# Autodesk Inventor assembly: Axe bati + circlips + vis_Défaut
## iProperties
Shininess: 64.0
Length Units: 11269
Angle Units: 11279
Time Units: 11290
Mass Units: 11283
Length Display Precision: 3
Angle Display Precision: 2
Compacted: True
Created: 2006-11
Part Number: Axe bati + circlips + vis_Défaut
Document SubType Name: Assembly
Designer: profs_sti
Density: 0.0
Volumn: 0.0
Area: 0.0
PropertySet Name: Model Information
Control State: 0
Master: False
Checked Out: False
Author: profs_sti
